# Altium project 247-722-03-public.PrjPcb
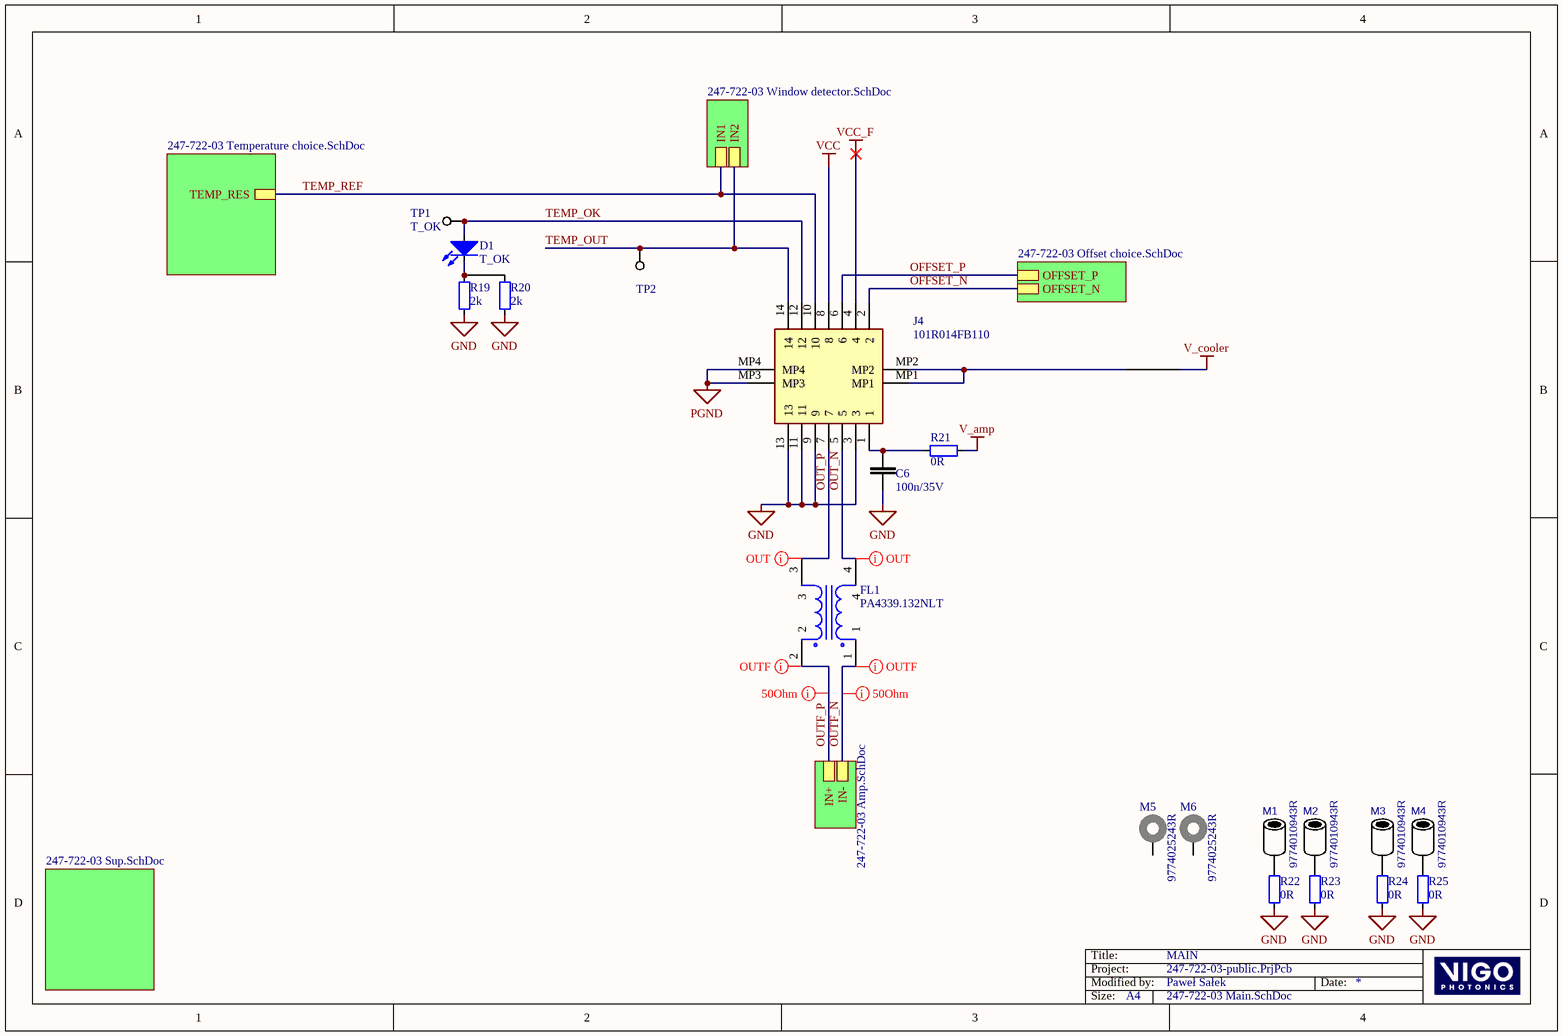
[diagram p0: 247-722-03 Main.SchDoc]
PCBNumber: 247-722-03; PCBRevision: 247-722-03; ProjectNumber: 247
7 sheets, 113 parts. Net scope: hierarchical (ports join the sheet entries above them; power ports are global).
Board file: 247-722-03.PcbDoc
Sheets:
  247-722-03 Main.SchDoc
    SUP_MAIN = 247-722-03 Sup.SchDoc
    Window comparator = 247-722-03 Window detector.SchDoc
    TEMPERATURE = 247-722-03 Temperature choice.SchDoc
    OFFSET = 247-722-03 Offset choice.SchDoc
    AMP = 247-722-03 Amp.SchDoc
      SUP_AMP = 247-722-03 Amp_sup.SchDoc

## Sheet 247-722-03 Main.SchDoc: MAIN
size A4; Author: psalek; DrawnBy: PS; Engineer: Paweł Sałek; Organization: VIGO System S.A.; Address1: ul. Poznańska 129/133; Address2: 05-580 Ozarów Mazowiecki; Address3: POLAND; DocumentNumber: aaaa; Revision: 01; SheetNumber: 1; SheetTotal: 7

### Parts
C6  100n/35V  [0402_CAP]
D1  T_OK  [0402_LED_G]
FL1  PA4339.132NLT  [PA4339132NLT]
J4  101R014FB110  [101R014FB110]
M1  9774010943R  [TP_THT_1500_3000]
M2  9774010943R  [TP_THT_1500_3000]
M3  9774010943R  [TP_THT_1500_3000]
M4  9774010943R  [TP_THT_1500_3000]
M5  9774025243R  [9774025243]
M6  9774025243R  [9774025243]
R19  2k  [0402_RES]
R20  2k  [0402_RES]
R21  0R  [0402_RES]
R22  0R  [0402_RES]
R23  0R  [0402_RES]
R24  0R  [0402_RES]
R25  0R  [0402_RES]
TP1  T_OK  [TP_2]  (no BOM)
TP2  (no value)  [TP_2]  (no BOM)

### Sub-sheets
AMP = 247-722-03 Amp.SchDoc: IN+, IN-
OFFSET = 247-722-03 Offset choice.SchDoc: OFFSET_N, OFFSET_P
SUP_MAIN = 247-722-03 Sup.SchDoc: no entries
TEMPERATURE = 247-722-03 Temperature choice.SchDoc: TEMP_RES
Window comparator = 247-722-03 Window detector.SchDoc: IN1, IN2

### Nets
GND: C6.1 J4.3 J4.9 J4.11 J4.13 R19.1 R20.1 R22.1 R23.1 R24.1 R25.1
PGND: J4.MP3 J4.MP4
V_amp: R21.2
V_cooler: J4.MP1 J4.MP2
VCC: J4.8
VCC_F: J4.4
OFFSET_N: J4.2 ; sheet OFFSET/OFFSET_N
OFFSET_P: J4.6 ; sheet OFFSET/OFFSET_P
OUT_N: FL1.4 J4.5
OUT_P: FL1.3 J4.7
OUTF_N: FL1.1 ; sheet AMP/IN-
OUTF_P: FL1.2 ; sheet AMP/IN+
TEMP_OK: D1.1(A) J4.12 TP1.1(TP)
TEMP_OUT: J4.14 TP2.1(TP) ; sheet Window comparator/IN2
TEMP_REF: J4.10 ; sheet Window comparator/IN1, sheet TEMPERATURE/TEMP_RES
NetC6_2: C6.2 J4.1 R21.1
NetD1_2: D1.2(K) R19.2 R20.2
NetM1_1: M1.1 R22.2
NetM2_1: M2.1 R23.2
NetM3_1: M3.1 R24.2
NetM4_1: M4.1 R25.2

Not connected (* = marked no-connect by the designer): M5 1; M6 1

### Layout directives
differential pair; rule Matched Net Lengths [Tolerance = 2mm]: OUT_N, OUT_P
differential pair: OUTF_N, OUTF_P
rule Impedance Constraint [Min = 47.00    Max = 53.00    ]: OUTF_N, OUTF_P

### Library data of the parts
C6 = cap_0402_100n_35V: Ceramic capacitor; Manufacturer: Taiyo Yuden; SMDorTHT: SMD
D1 = d_LED_0402_G: Manufacturer: Kinbright; Value: KPG-1005VGC-TT; SMDorTHT: SMD; pp_waste: 30
FL1 = b_PA4339.132NLT: Filter; Manufacturer_Name: Pulse; SMDorTHT: SMD
J4 = j_101R014FB110: 14pin + 2 power paths, 0.35mm pitch; Manufacturer_Name: Amphenol ICC / Aorora; Manufacturer: Amphenol ICC; SMDorTHT: SMD
M1-M4 = m_spacer_1mm_fi2.25_WA-SMST_9774010943: Manufacturer: Wurth Elektronik; SMDorTHT: SMD
M5 M6 = m_spacer_2.5mm_fi2.25_WA_SMT_9774025243: WA-SMSI SMT Steel Spacer, internal Thread, OD 4.35mm, M2x2.5mm; Manufacturer: Wurth Elektronik; Inner Diameter: 2.8mm; Surface: Tin; Thread: M2; SMDorTHT: SMD
R19 R20 = res_0402_2k: Resistior; SMDorTHT: SMD; pp_waste: 30
R21-R25 = res_0402_0R: Resistior; SMDorTHT: SMD; pp_waste: 30
TP1 TP2 = m_TP_2: Test Point; Part Name: m_TP_2; SMDorTHT: noB

## Sheet 247-722-03 Sup.SchDoc: Power Supply
size A4; Author: psalek; DrawnBy: PS; Engineer: Paweł Sałek; Organization: VIGO System S.A.; Address1: ul. Poznańska 129/133; Address2: 05-580 Ozarów Mazowiecki; Address3: POLAND; Revision: 01; SheetNumber: 5; SheetTotal: 7
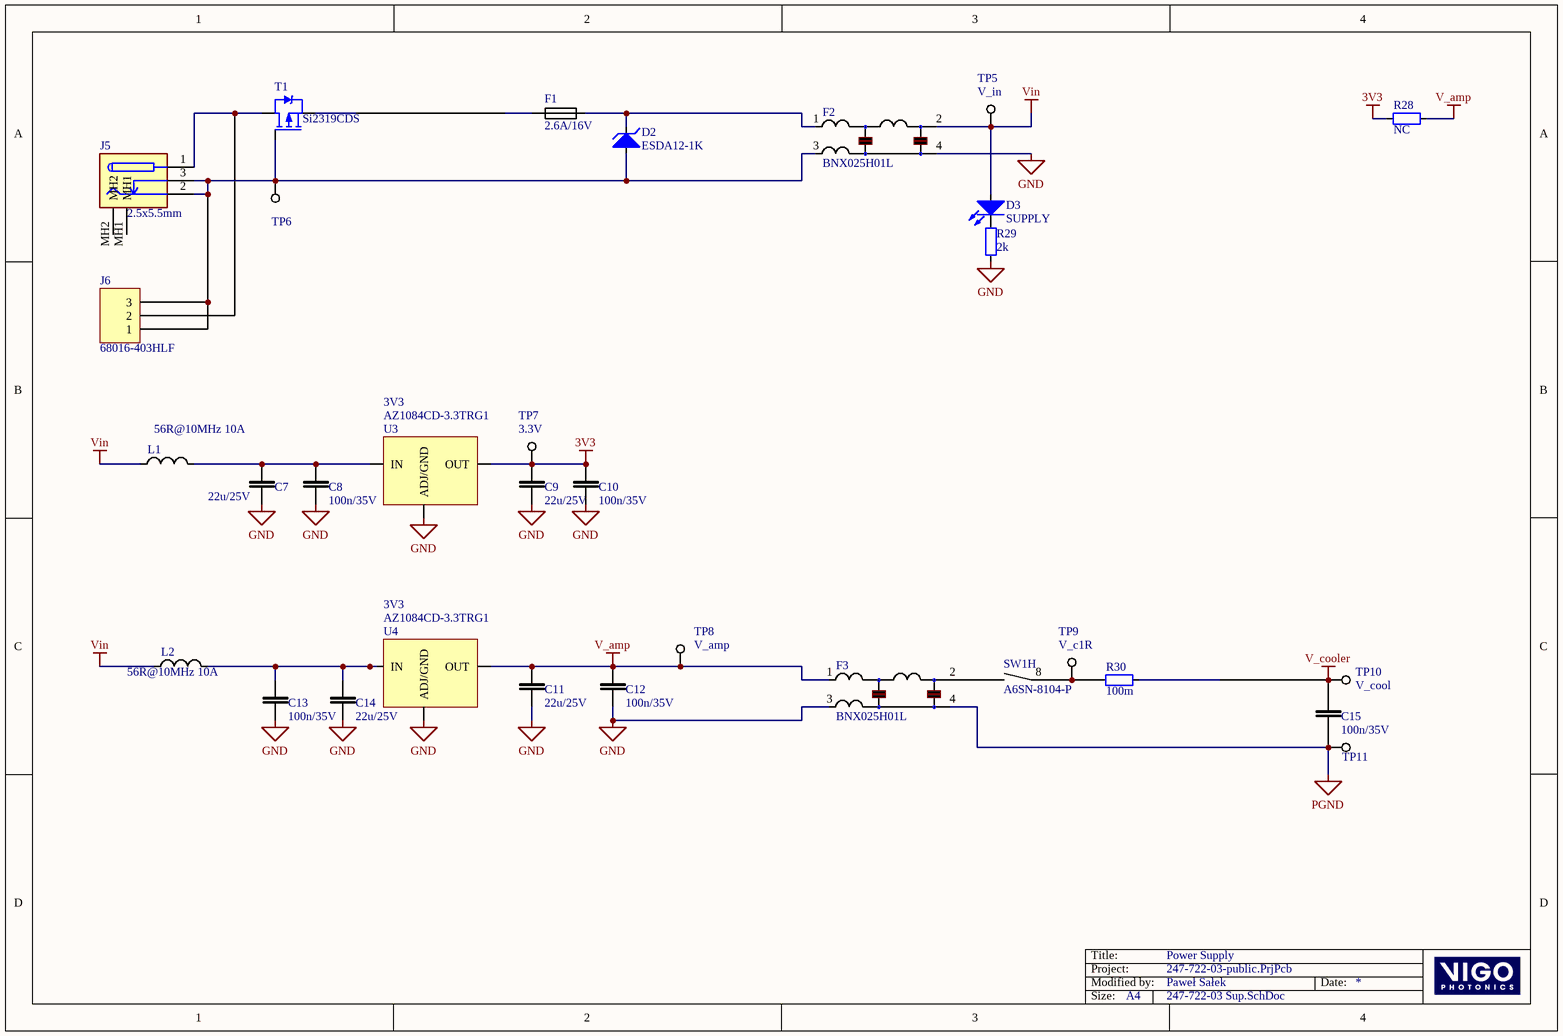
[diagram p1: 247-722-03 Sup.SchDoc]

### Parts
C7  22u/25V  [1206_CAP_H]
C8  100n/35V  [0402_CAP]
C9  22u/25V  [1206_CAP_H]
C10  100n/35V  [0402_CAP]
C11  22u/25V  [1206_CAP_H]
C12  100n/35V  [0402_CAP]
C13  100n/35V  [0402_CAP]
C14  22u/25V  [1206_CAP_H]
C15  100n/35V  [0402_CAP]
D2  ESDA12-1K  [SOD523]
D3  SUPPLY  [0402_LED_G]
F1  2.6A/16V  [1812_FUSE]
F2  BNX025H01L  [BNX025]
F3  BNX025H01L  [BNX025]
J5  2.5x5.5mm  [PJ079BH]
J6  68016-403HLF  [HDR_100mil_1x3M_RA]
L1  56R@10MHz 10A  [1612_EMI]
L2  56R@10MHz 10A  [1612_EMI]
R28  NC  [0603_RES]  (no BOM)
R29  2k  [0402_RES]
R30  100m  [0402_RES]
SW1  A6SN-8104-P  [SW_A6SN-8101_OMR]  (part H of 8)
T1  Si2319CDS  [SOT23-GSD]
TP5  V_in  [TP_2]  (no BOM)
TP6  (no value)  [TP_2]  (no BOM)
TP7  3.3V  [TP_2]  (no BOM)
TP8  V_amp  [TP_2]  (no BOM)
TP9  V_c1R  [TP_2]  (no BOM)
TP10  V_cool  [TP_2]  (no BOM)
TP11  (no value)  [TP_2]  (no BOM)
U3  3V3  value AZ1084CD-3.3TRG1  [TO252]
U4  3V3  value AZ1084CD-3.3TRG1  [TO252]

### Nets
3V3: C9.2 C10.2 R28.1 TP7.1(TP) U3.2(OUT)
GND: C7.1 C8.1 C9.1 C10.1 C11.1 C12.1 C13.1 C14.1 F2.4(CG) F3.3(PSG) R29.2 U3.1(ADJ/GND) U4.1(ADJ/GND)
PGND: C15.1 F3.4(CG) TP11.1(TP)
V_amp: C11.2 C12.2 F3.1(B) R28.2 TP8.1(TP) U4.2(OUT)
V_cooler: C15.2 R30.2 TP10.1(TP)
Vin: D3.1(A) F2.2(CB) L1.1 L2.1 TP5.1(TP)
NetC7_2: C7.2 C8.2 L1.2 U3.3(IN)
NetC13_2: C13.2 C14.2 L2.2 U4.3(IN)
NetD2_1: D2.1(A) F2.3(PSG) J5.2 J5.3 J6.1 J6.3 T1.1(G) TP6.1(TP)
NetD2_2: D2.2(K) F1.2 F2.1(B)
NetD3_2: D3.2(K) R29.1
NetF1_1: F1.1 T1.3(S)
NetF3_2: F3.2(CB) SW1.9
NetJ5_1: J5.1 J6.2 T1.2(D)
NetR30_1: R30.1 SW1.8 TP9.1(TP)

Not connected (* = marked no-connect by the designer): J5 MH1 MH2

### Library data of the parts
C7 C9 C11 C14 = cap_1206_22u_25V: Ceramic capacitor; SMDorTHT: SMD; pp_waste: 5
C8 C10 C12 C13 C15 = cap_0402_100n_35V: as C6 on sheet 247-722-03 Main
D2 = d_TVS_ESDA12-1K: Manufacturer: Diodes Incorporated; SMDorTHT: SMD; pp_waste: 5
D3 = d_LED_0402_G: as D1 on sheet 247-722-03 Main
F1 = f_PTC_1812_2A6_16V: SMDorTHT: SMD; pp_waste: 10
F2 F3 = fil_BNX025H01L: Manufacturer: Murata; SMDorTHT: SMD; pp_waste: 2
J5 = j_PJ-079BH: Connector; Manufacturer_Name: CUI Inc.; Manufacturer: CUI Devices; Value: PJ079BH; SMDorTHT: THT
J6 = j_HDR_100mil_1x3_RA: Header, 3-Pin; Manufacturer: Amphenol; SMDorTHT: THT
L1 L2 = l_1612_EMI_56R_10A: DO5040H-103; SMDorTHT: SMD; pp_waste: 5
R28 = res_0603_NC: Resistior
R29 = res_0402_2k: Resistior; SMDorTHT: SMD; pp_waste: 30
R30 = res_0402_0R10: Resistior; Manufacturer: YAGEO; SMDorTHT: SMD
SW1 = s_DIP_8_S: No Description Available; Mfr_Name: Omron; SMDorTHT: SMD
T1 = t_Si2319CDS: Manufacturer: Vishay; SMDorTHT: SMD; pp_waste: 10
TP5-TP11 = m_TP_2: as TP1 on sheet 247-722-03 Main
U3 U4 = ic_AZ1084CD-3.3TRG1: 3-TERMINAL  LDO; Manufacturer: DIODES Incorporated; SMDorTHT: SMD

## Sheet 247-722-03 Window detector.SchDoc: Window detector
size A4; Author: psalek; DrawnBy: PS; Engineer: Paweł Sałek; Organization: VIGO System S.A.; Address1: ul. Poznańska 129/133; Address2: 05-580 Ozarów Mazowiecki; Address3: POLAND; Revision: 01; SheetNumber: 7; SheetTotal: 7
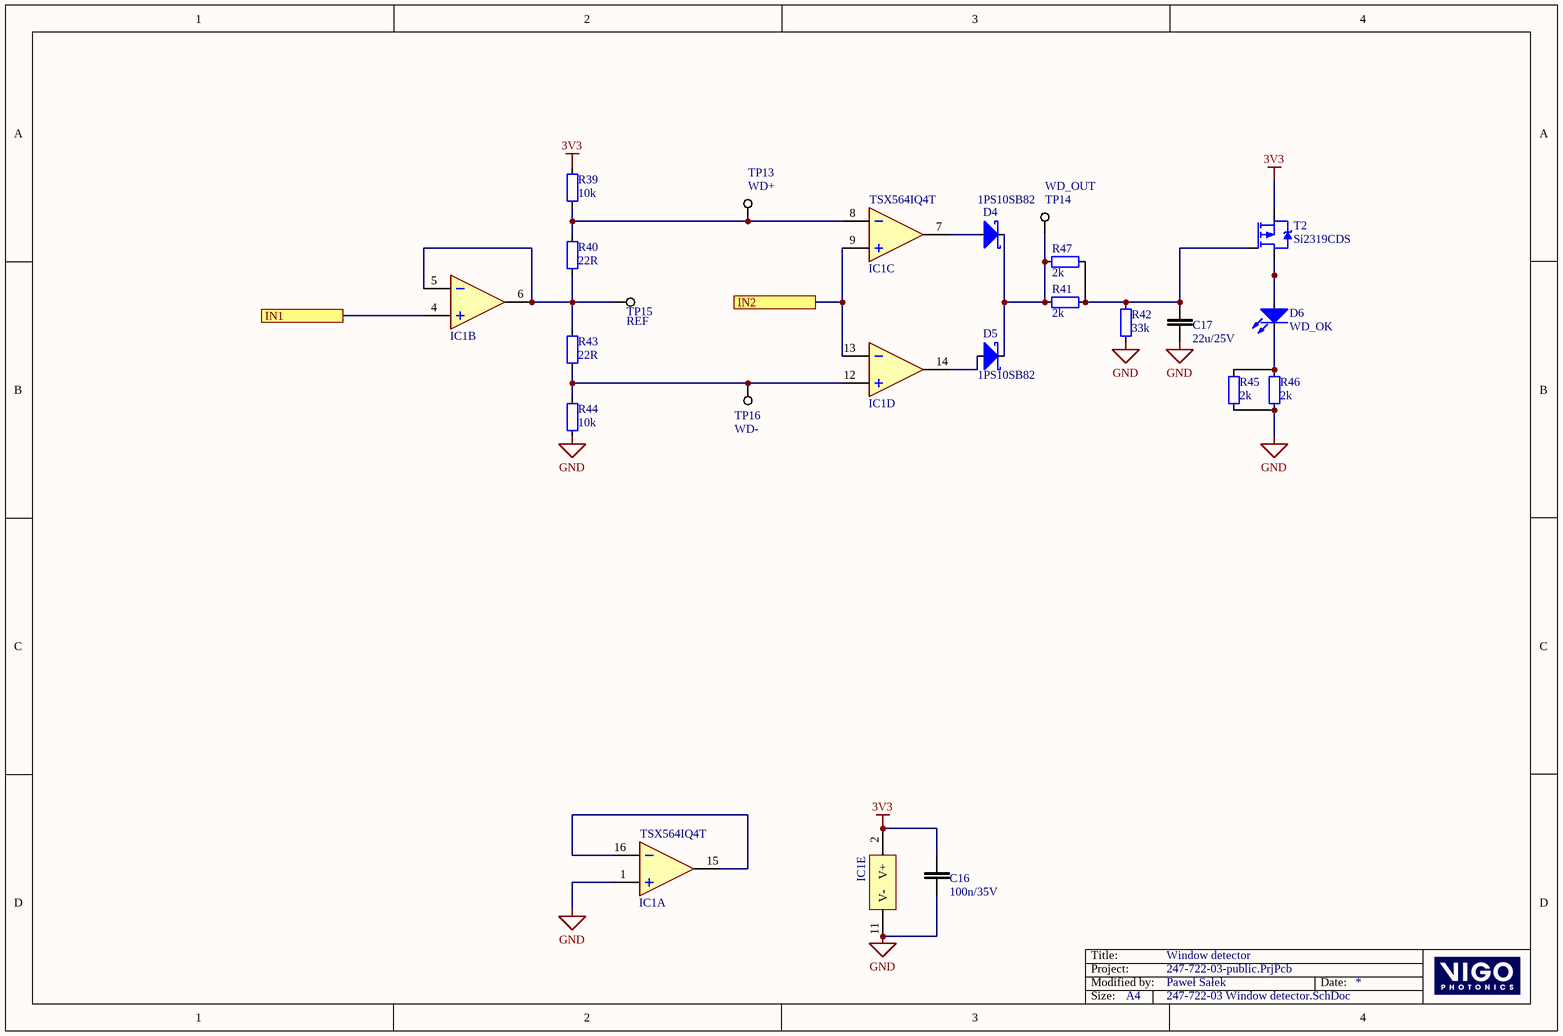
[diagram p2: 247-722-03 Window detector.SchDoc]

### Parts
C16  100n/35V  [0402_CAP]
C17  22u/25V  [1206_CAP_H]
D4  1PS10SB82  [DFN-1006-2]
D5  1PS10SB82  [DFN-1006-2]
D6  WD_OK  [0402_LED_G]
IC1  TSX564IQ4T  [QFN16]  (parts A,B,C,D,E of 5)
R39  10k  [0402_RES]
R40  22R  [0402_RES]
R41  2k  [0402_RES]
R42  33k  [0402_RES]
R43  22R  [0402_RES]
R44  10k  [0402_RES]
R45  2k  [0402_RES]
R46  2k  [0402_RES]
R47  2k  [0402_RES]
T2  Si2319CDS  [SOT23-GSD]
TP13  WD+  [TP_2]  (no BOM)
TP14  WD_OUT  [TP_2]  (no BOM)
TP15  REF  [TP_2]  (no BOM)
TP16  WD-  [TP_2]  (no BOM)

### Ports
IN1, IN2

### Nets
3V3: C16.2 IC1.2(V+) R39.2 T2.3(S)
GND: C16.1 C17.1 IC1.1(IN+) IC1.11(V-) R42.2 R44.2 R45.2 R46.2
TEMP_OUT: IC1.9(IN+) IC1.13(IN-) ; port IN2
TEMP_REF: IC1.4(IN+) ; port IN1
NetC17_2: C17.2 R41.1 R42.1 R47.1 T2.1(G)
NetD4_1: D4.1(A) IC1.7(OUT)
NetD4_2: D4.2(K) D5.2(K) R41.2 R47.2 TP14.1(TP)
NetD5_1: D5.1(A) IC1.14(OUT)
NetD6_1: D6.1(A) T2.2(D)
NetD6_2: D6.2(K) R45.1 R46.1
NetIC1_5: IC1.5(IN-) IC1.6(IN+) R40.1 R43.2 TP15.1(TP)
NetIC1_8: IC1.8(IN-) R39.1 R40.2 TP13.1(TP)
NetIC1_12: IC1.12(IN+) R43.1 R44.1 TP16.1(TP)
NetIC1_15: IC1.15(OUT) IC1.16(IN-)

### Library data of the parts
C16 = cap_0402_100n_35V: as C6 on sheet 247-722-03 Main
C17 = cap_1206_22u_25V: as C7 on sheet 247-722-03 Sup
D4 D5 = d_1PS10SB82: Schottky barrier diode, low capacitance (1pF); Manufacturer: Nexperia; SMDorTHT: SMD
D6 = d_LED_0402_G: as D1 on sheet 247-722-03 Main
IC1 = ic_TSX564IQ4T: quad rail-to-rail precision opamp; Manufacturer: ST; SMDorTHT: SMD
R39 R44 = res_0402_10k: Resistior; SMDorTHT: SMD; pp_waste: 30
R40 R43 = res_0402_22R: Resistior; SMDorTHT: SMD; pp_waste: 30
R41 R45-R47 = res_0402_2k: Resistior; SMDorTHT: SMD; pp_waste: 30
R42 = res_0402_33k: Resistior; SMDorTHT: SMD; pp_waste: 30
T2 = t_Si2319CDS: as T1 on sheet 247-722-03 Sup
TP13-TP16 = m_TP_2: as TP1 on sheet 247-722-03 Main

## Sheet 247-722-03 Temperature choice.SchDoc: Temperature choice
size A4; Author: psalek; DrawnBy: PS; Engineer: Paweł Sałek; Organization: VIGO System S.A.; Address1: ul. Poznańska 129/133; Address2: 05-580 Ozarów Mazowiecki; Address3: POLAND; Revision: 01; SheetNumber: 7; SheetTotal: 8
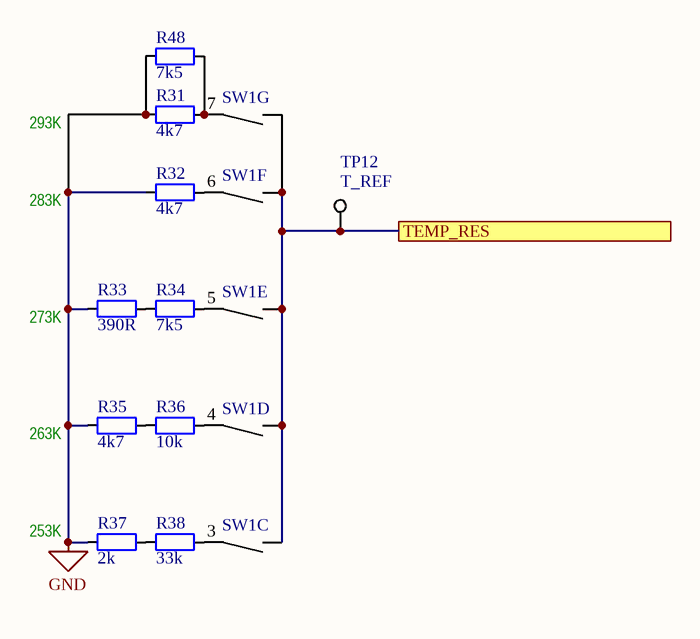
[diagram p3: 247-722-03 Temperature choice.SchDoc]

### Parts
R31  4k7  [0402_RES]
R32  4k7  [0402_RES]
R33  390R  [0402_RES]
R34  7k5  [0402_RES]
R35  4k7  [0402_RES]
R36  10k  [0402_RES]
R37  2k  [0402_RES]
R38  33k  [0402_RES]
R48  7k5  [0402_RES]
SW1  A6SN-8104-P  [SW_A6SN-8101_OMR]  (value not drawn)  (parts C,D,E,F,G of 8)
TP12  T_REF  [TP_2]  (no BOM)

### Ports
TEMP_RES

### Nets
GND: R31.1 R32.1 R33.1 R35.1 R37.1 R48.1
TEMP_REF: SW1.10 SW1.11 SW1.12 SW1.13 SW1.14 TP12.1(TP) ; port TEMP_RES
NetR31_2: R31.2 R48.2 SW1.7
NetR32_2: R32.2 SW1.6
NetR33_2: R33.2 R34.1
NetR34_2: R34.2 SW1.5
NetR35_2: R35.2 R36.1
NetR36_2: R36.2 SW1.4
NetR37_2: R37.2 R38.1
NetR38_2: R38.2 SW1.3

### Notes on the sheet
- 293K
- 283K
- (near R33) 273K
- (near R35) 263K
- (near R37) 253K

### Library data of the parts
R31 R32 R35 = res_0402_4k7: Resistior; SMDorTHT: SMD; pp_waste: 30
R33 = res_0402_390R: Resistior; SMDorTHT: SMD; pp_waste: 30
R34 R48 = res_0402_7k5: Resistior; SMDorTHT: SMD; pp_waste: 30
R36 = res_0402_10k: Resistior; SMDorTHT: SMD; pp_waste: 30
R37 = res_0402_2k: Resistior; SMDorTHT: SMD; pp_waste: 30
R38 = res_0402_33k: Resistior; SMDorTHT: SMD; pp_waste: 30
SW1 = s_DIP_8_S: as SW1 on sheet 247-722-03 Sup
TP12 = m_TP_2: as TP1 on sheet 247-722-03 Main

## Sheet 247-722-03 Offset choice.SchDoc: Offset choice
size A4; Author: psalek; DrawnBy: PS; Engineer: Paweł Sałek; Organization: VIGO System S.A.; Address1: ul. Poznańska 129/133; Address2: 05-580 Ozarów Mazowiecki; Address3: POLAND; Revision: 01; SheetNumber: 4; SheetTotal: 8
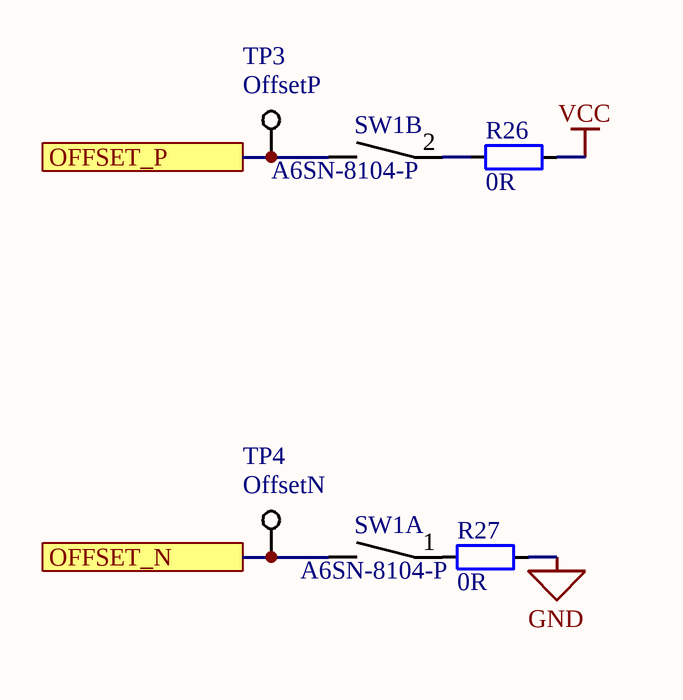
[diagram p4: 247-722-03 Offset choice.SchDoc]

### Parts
R26  0R  [0402_RES]
R27  0R  [0402_RES]
SW1  A6SN-8104-P  [SW_A6SN-8101_OMR]  (parts A,B of 8)
TP3  OffsetP  [TP_2]  (no BOM)
TP4  OffsetN  [TP_2]  (no BOM)

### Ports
OFFSET_N, OFFSET_P

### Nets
GND: R27.2
VCC: R26.2
OFFSET_N: SW1.16 TP4.1(TP) ; port OFFSET_N
OFFSET_P: SW1.15 TP3.1(TP) ; port OFFSET_P
NetR26_1: R26.1 SW1.2
NetR27_1: R27.1 SW1.1

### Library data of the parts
R26 R27 = res_0402_0R: Resistior; SMDorTHT: SMD; pp_waste: 30
SW1 = s_DIP_8_S: as SW1 on sheet 247-722-03 Sup
TP3 TP4 = m_TP_2: as TP1 on sheet 247-722-03 Main

## Sheet 247-722-03 Amp.SchDoc: Amplifier
size A4; Author: psalek; DrawnBy: PS; Engineer: Paweł Sałek; Organization: VIGO System S.A.; Address1: ul. Poznańska 129/133; Address2: 05-580 Ozarów Mazowiecki; Address3: POLAND; Revision: 01; SheetNumber: 2; SheetTotal: 7
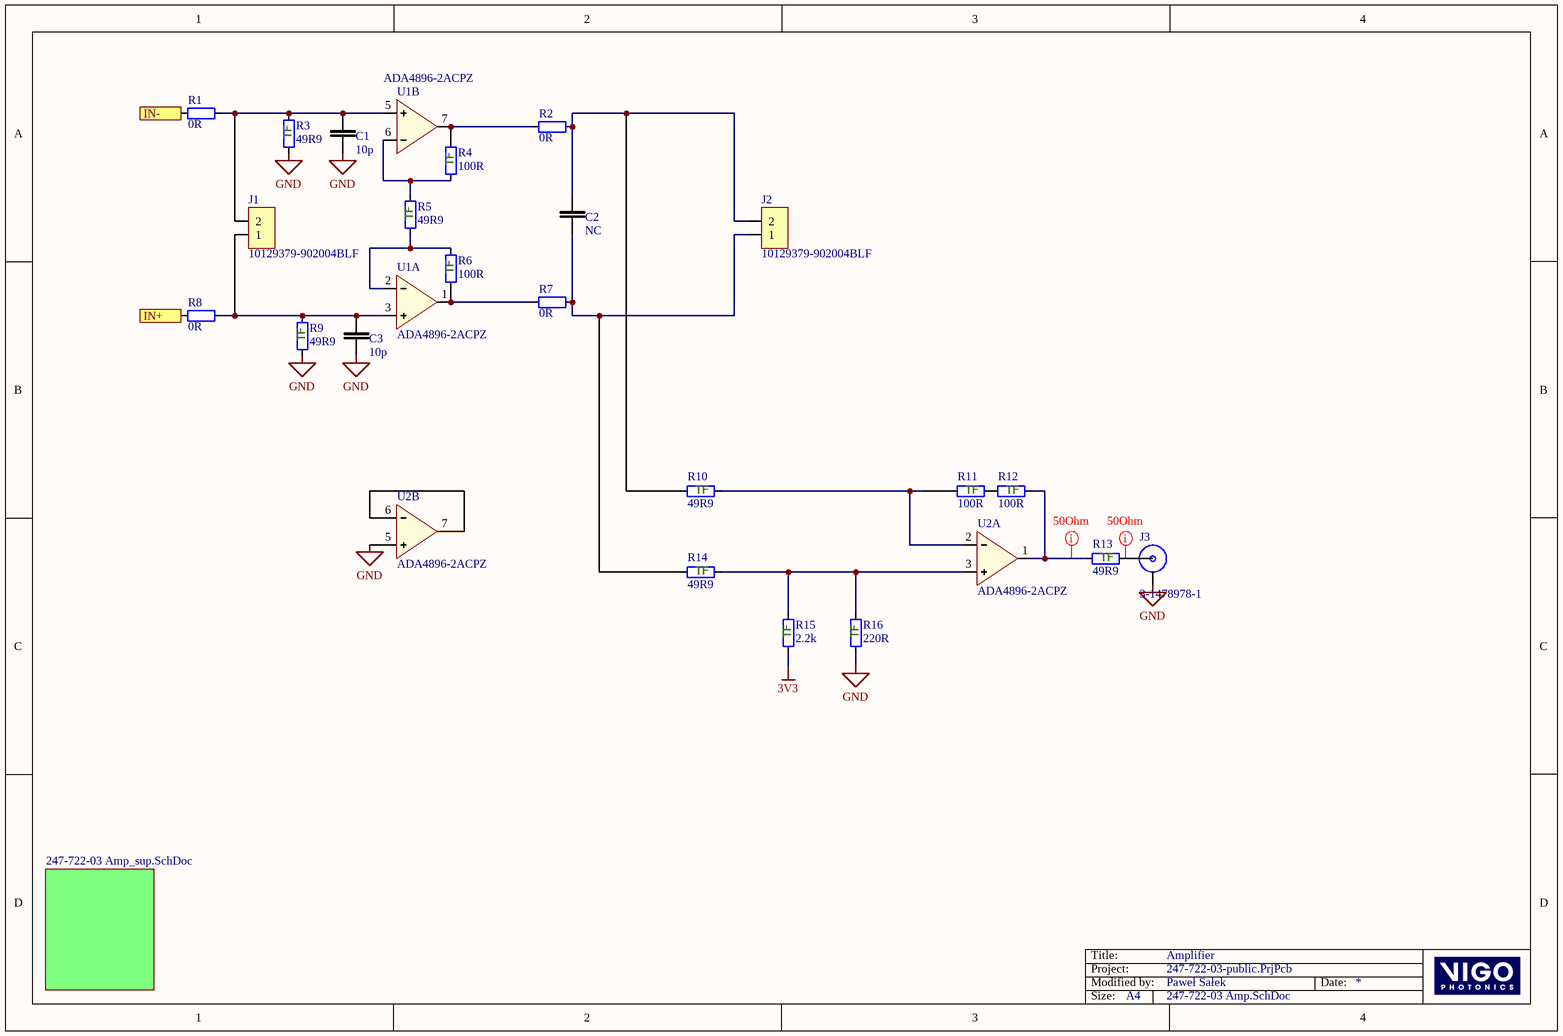
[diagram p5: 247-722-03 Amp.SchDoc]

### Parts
C1  10p  [0402_CAP]
C2  NC  [0402_CAP]  (no BOM)
C3  10p  [0402_CAP]
J1  10129379-902004BLF  [HDR_100mil_1x2M_RA]
J2  10129379-902004BLF  [HDR_100mil_1x2M_RA]
J3  3-1478978-1  [SMA_ 3-1478978-1]
R1  0R  [0402_RES]
R2  0R  [0402_RES]
R3  49R9  [0402_RES]
R4  100R  [0402_RES]
R5  49R9  [0402_RES]
R6  100R  [0402_RES]
R7  0R  [0402_RES]
R8  0R  [0402_RES]
R9  49R9  [0402_RES]
R10  49R9  [0402_RES]
R11  100R  [0402_RES]
R12  100R  [0402_RES]
R13  49R9  [0402_RES]
R14  49R9  [0402_RES]
R15  2.2k  [0402_RES]
R16  220R  [0402_RES]
U1  ADA4896-2ACPZ  [LFCSP-8]  (parts A,B of 3)
U2  ADA4896-2ACPZ  [LFCSP-8]  (parts A,B of 3)

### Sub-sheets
SUP_AMP = 247-722-03 Amp_sup.SchDoc: no entries

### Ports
IN+, IN-

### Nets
3V3: R15.1
GND: C1.1 C3.1 J3.2 R3.1 R9.1 R16.1 U2.5(+IN2)
OUTF_N: R1.1 ; port IN-
OUTF_P: R8.1 ; port IN+
NetC1_2: C1.2 J1.2 R1.2 R3.2 U1.5(+IN2)
NetC2_1: C2.1 J2.1 R7.2 R14.1
NetC2_2: C2.2 J2.2 R2.2 R10.1
NetC3_2: C3.2 J1.1 R8.2 R9.2 U1.3(+IN1)
NetJ3_1: J3.1 R13.2
NetR2_1: R2.1 R4.2 U1.7(OUT2)
NetR4_1: R4.1 R5.2 U1.6(-IN2)
NetR5_1: R5.1 R6.2 U1.2(-IN1)
NetR6_1: R6.1 R7.1 U1.1(OUT1)
NetR10_2: R10.2 R11.1 U2.2(-IN1)
NetR11_2: R11.2 R12.1
NetR12_2: R12.2 R13.1 U2.1(OUT1)
NetR14_2: R14.2 R15.2 R16.2 U2.3(+IN1)
NetU2_6: U2.6(-IN2) U2.7(OUT2)

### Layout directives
rule Impedance Constraint [Min = 47.00    Max = 53.00    ]: NetJ3_1, NetR12_2

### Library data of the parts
C1 C3 = cap_0402_10p: Ceramic capacitor; SMDorTHT: SMD; pp_waste: 30
C2 = cap_0402_4p7_50V: Ceramic capacitor; SMDorTHT: SMD; pp_waste: 30
J1 J2 = j_HDR_100mil_1x2_RA: Header, 2-Pin; Manufacturer: Amphenol; SMDorTHT: THT
J3 = j_SMA_3-1478978-1: Manufacturer: TE Connectivity; SMDorTHT: THT; pp_waste: 1
R1 R2 R7 R8 = res_0402_0R: Resistior; SMDorTHT: SMD; pp_waste: 30
R3 R5 R9 R10 R13 R14 = res_49R9/0.1%/TF: Resistior; Manufacturer: Yageo; SMDorTHT: SMD
R4 R6 R11 R12 = res_0402_100R/0.1%/TF: Resistior; Manufacturer: Yageo; SMDorTHT: SMD
R15 = res_0402_2.2k/0.1%/TF: Resistior; Manufacturer: Yageo; SMDorTHT: SMD
R16 = res_0402_220R/0.1%/TF: Resistior; Manufacturer: Yageo; SMDorTHT: SMD
U1 U2 = ic_ADA4896-2: opamp; Manufacturer: Analog Devices; SMDorTHT: SMD

## Sheet 247-722-03 Amp_sup.SchDoc: Amplifier supply decoupling
size A4; Author: psalek; DrawnBy: PS; Engineer: Paweł Sałek; Organization: VIGO System S.A.; Address1: ul. Poznańska 129/133; Address2: 05-580 Ozarów Mazowiecki; Address3: POLAND; Revision: 01; SheetNumber: 3; SheetTotal: 7
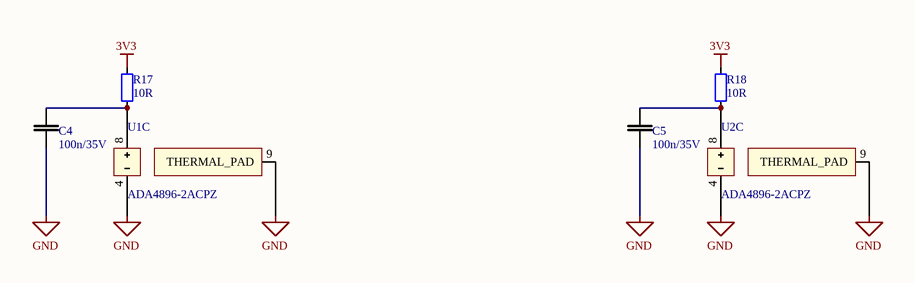
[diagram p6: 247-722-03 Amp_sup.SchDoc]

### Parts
C4  100n/35V  [0402_CAP]
C5  100n/35V  [0402_CAP]
R17  10R  [0402_RES]
R18  10R  [0402_RES]
U1  ADA4896-2ACPZ  [LFCSP-8]  (part C of 3)
U2  ADA4896-2ACPZ  [LFCSP-8]  (part C of 3)

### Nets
3V3: R17.2 R18.2
GND: C4.1 C5.1 U1.4(V-) U1.9(THERMAL_PAD) U2.4(V-) U2.9(THERMAL_PAD)
NetC4_2: C4.2 R17.1 U1.8(V+)
NetC5_2: C5.2 R18.1 U2.8(V+)

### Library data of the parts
C4 C5 = cap_0402_100n_35V: as C6 on sheet 247-722-03 Main
R17 R18 = res_0402_10R: Resistior; SMDorTHT: SMD; pp_waste: 30
U1 U2 = ic_ADA4896-2: as U1 on sheet 247-722-03 Amp

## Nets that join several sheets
3V3: 247-722-03 Sup (5 pins), 247-722-03 Window detector (C16.2 IC1.2 R39.2 T2.3), 247-722-03 Amp (R15.1), 247-722-03 Amp_sup (R17.2 R18.2)
GND: 247-722-03 Main (11 pins), 247-722-03 Sup (13 pins), 247-722-03 Window detector (8 pins), 247-722-03 Temperature choice (6 pins), 247-722-03 Offset choice (R27.2), 247-722-03 Amp (7 pins), 247-722-03 Amp_sup (6 pins)
PGND: 247-722-03 Main (J4.MP3 J4.MP4), 247-722-03 Sup (C15.1 F3.4 TP11.1)
V_amp: 247-722-03 Main (R21.2), 247-722-03 Sup (6 pins)
V_cooler: 247-722-03 Main (J4.MP1 J4.MP2), 247-722-03 Sup (C15.2 R30.2 TP10.1)
VCC: 247-722-03 Main (J4.8), 247-722-03 Offset choice (R26.2)
OFFSET_N: 247-722-03 Main (J4.2), 247-722-03 Offset choice (SW1.16 TP4.1)
OFFSET_P: 247-722-03 Main (J4.6), 247-722-03 Offset choice (SW1.15 TP3.1)
OUTF_N: 247-722-03 Main (FL1.1), 247-722-03 Amp (R1.1)
OUTF_P: 247-722-03 Main (FL1.2), 247-722-03 Amp (R8.1)
TEMP_OUT: 247-722-03 Main (J4.14 TP2.1), 247-722-03 Window detector (IC1.9 IC1.13)
TEMP_REF: 247-722-03 Main (J4.10), 247-722-03 Window detector (IC1.4), 247-722-03 Temperature choice (6 pins)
